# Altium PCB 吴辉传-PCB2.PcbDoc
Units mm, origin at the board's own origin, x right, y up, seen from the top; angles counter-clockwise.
Board outline 80 x 60 mm, 2 copper layers (Top Layer, Bottom Layer); 29 components, 19 nets, 66 pads, 0 vias.
Unrouted connection lines stored in the file: 47.
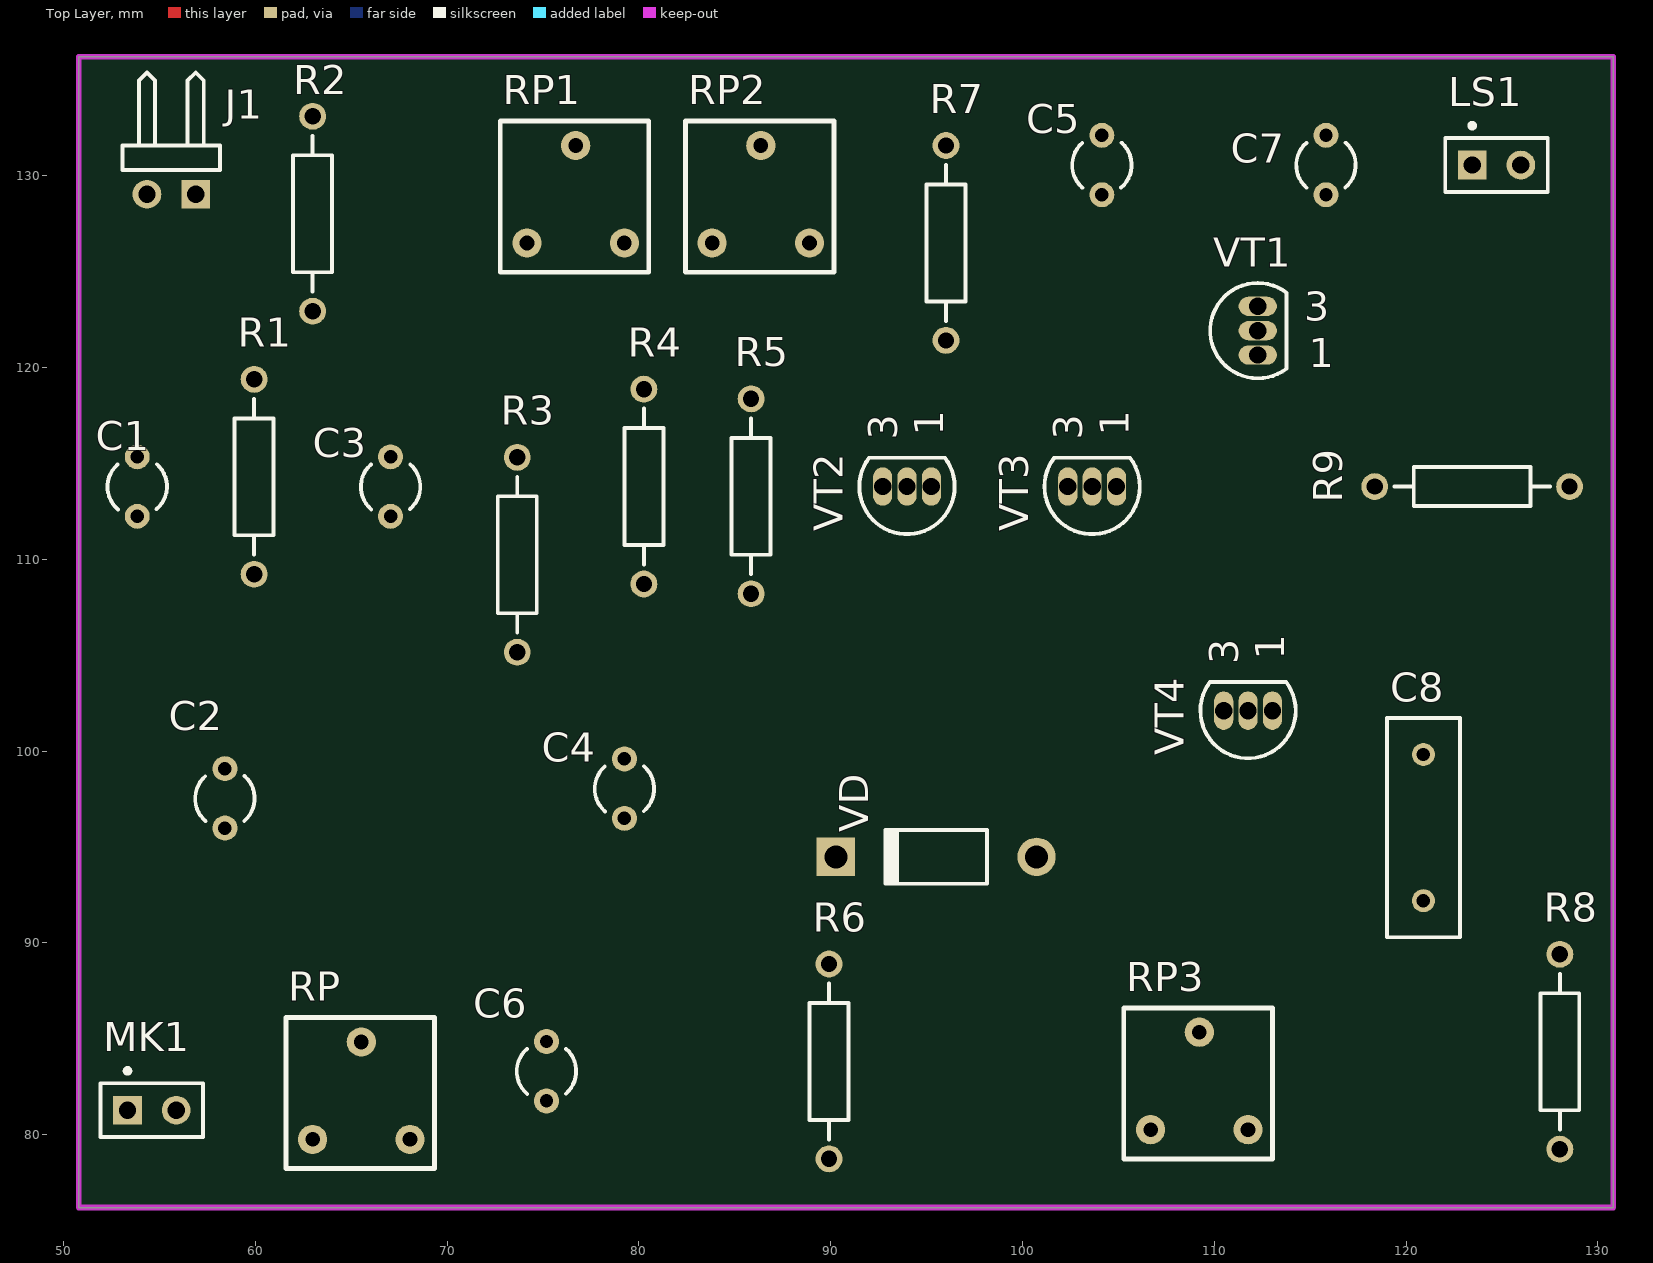
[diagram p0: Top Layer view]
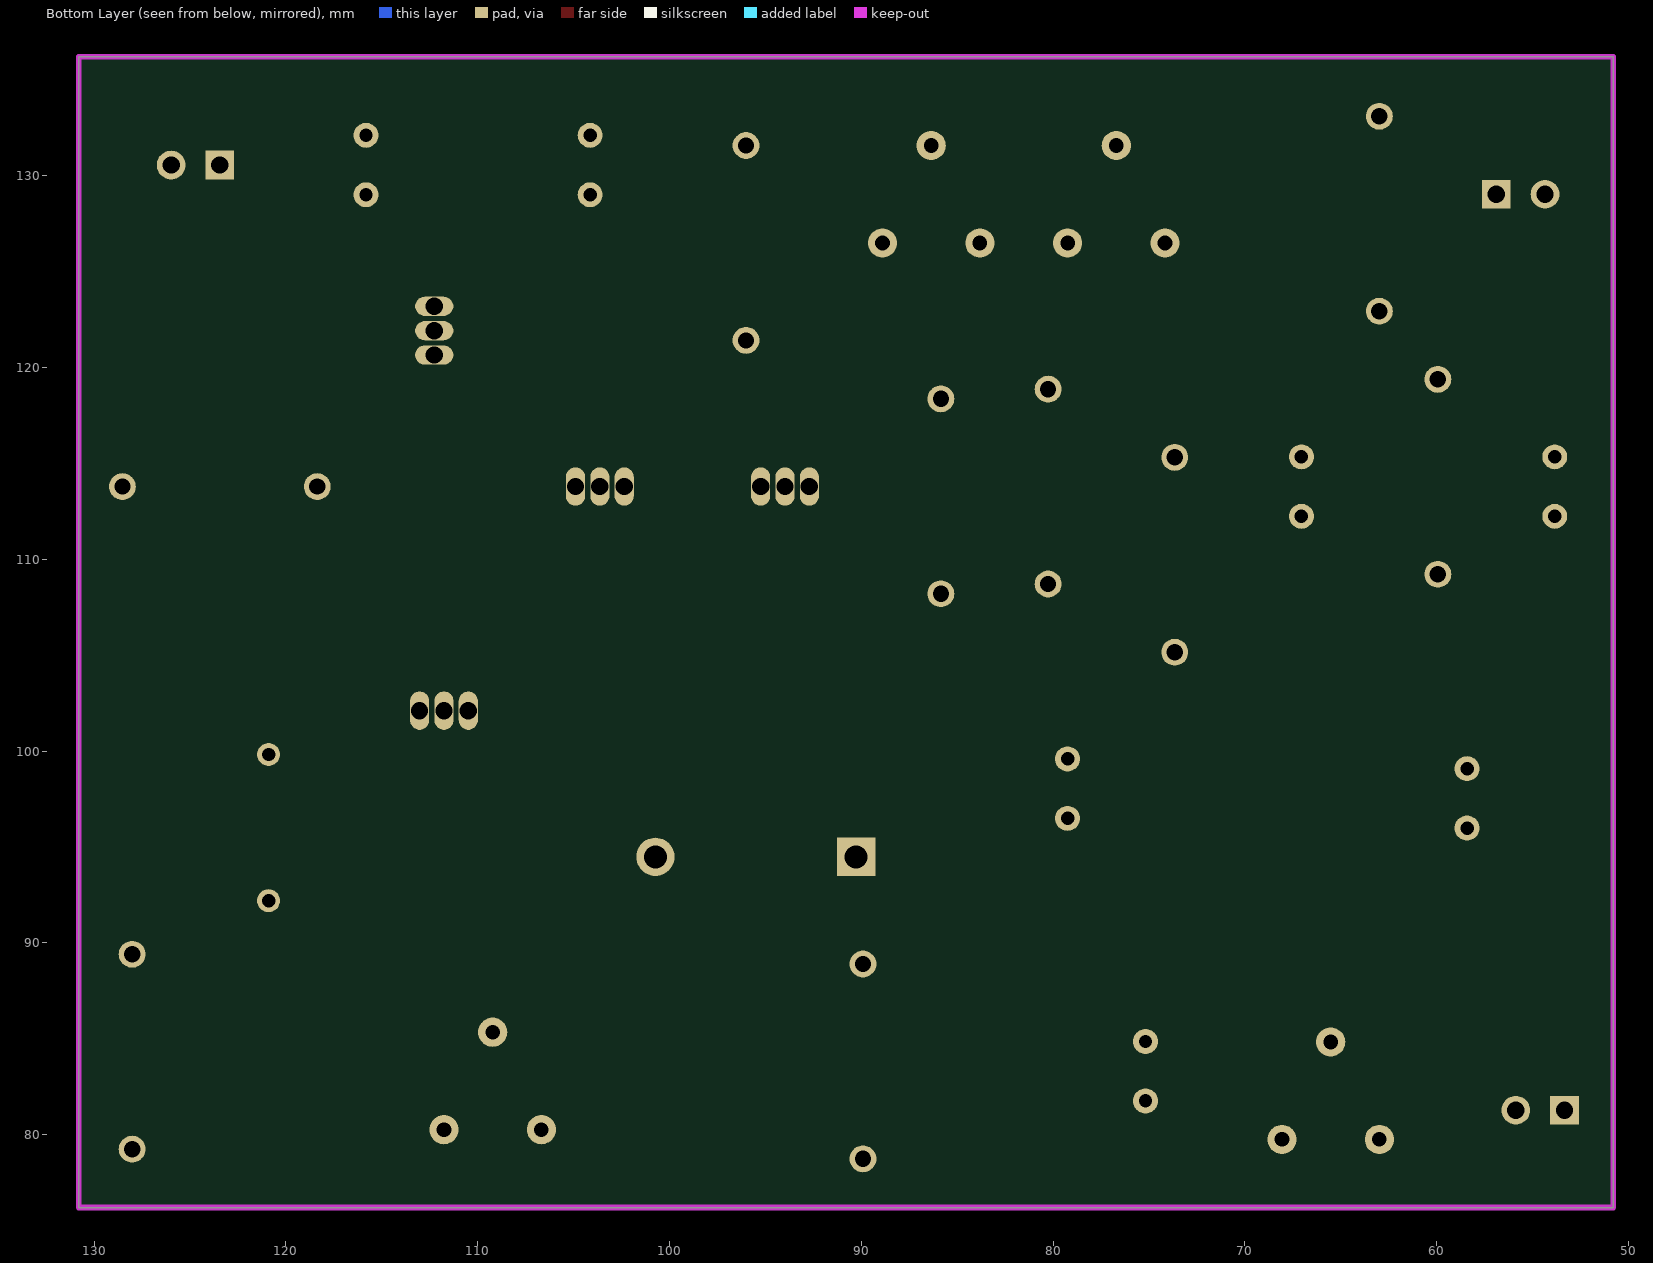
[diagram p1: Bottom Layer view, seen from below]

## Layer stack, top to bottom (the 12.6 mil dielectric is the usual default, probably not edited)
Top Layer: signal copper 0.0356
Dielectric: dielectric 0.32, FR-4, Dk 4.8
Bottom Layer: signal copper 0.0356

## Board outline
50.8,76.2 130.8,76.2 130.8,136.2 50.8,136.2

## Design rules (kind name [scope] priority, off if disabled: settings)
Clearance [All] p1: gap=0.2
ComponentClearance [All] p1: gap=0.254 collisioncheckmode=0
PolygonConnect [All] p1: connectstyle=Relief reliefconductorwidth=0.254 reliefentries=4 polygonreliefangle="90 Angle"
RoutingLayers [InNet('GND')] p1: top layer_v5=FALSE bottom layer_v5=TRUE
RoutingVias [All] p1: holewidth=0.6 width=1 viastyle="Through Hole" minholewidth=0.711 minwidth=1.27 maxholewidth=0.711 maxwidth=1.27
SolderMaskExpansion [All] p1: expansion=0.102
TestPointUsage [All] p1: valid=0 allowmultiple=FALSE
Testpoint [All] p1: side=15 testpointundercomponent=TRUE minsize=1.016 maxsize=2.54 preferedsize=1.524 minholesize=0 maxholesize=1.016 preferedholesize=0.813 testpointgrid=0.025 style=1023 order=1234567890
Width Width_2 [InNet('GND')] p1: maxlimit=1 minlimit=1 preferedwidth=1
Width Width_1 [InNet('VCC')] p2: maxlimit=1.5 minlimit=1.5 preferedwidth=1.5
Width [All] p3: maxlimit=1.2 minlimit=1.2 preferedwidth=1.2
16 further rules are at their usual default settings.

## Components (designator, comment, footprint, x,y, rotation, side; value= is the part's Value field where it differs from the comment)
C1 "10uF" BCY-W2/D3.1 53.848,113.792 r0 top
C2 "Cap Pol1" BCY-W2/D3.1 58.42,97.536 r0 top
C3 "Cap Pol1" BCY-W2/D3.1 67.056,113.792 r0 top
C4 "Cap Pol1" BCY-W2/D3.1 79.248,98.044 r0 top
C5 "Cap Pol1" BCY-W2/D3.1 104.14,130.556 r0 top
C6 "Cap Pol1" BCY-W2/D3.1 75.184,83.312 r0 top
C7 "Cap Pol1" BCY-W2/D3.1 115.824,130.556 r0 top
C8 "Cap" RAD-0.3 120.904,96.012 r90 top
J1 "MHDR1X" HDR1X2H 56.896,129.032 r180 top
LS1 "Speaker" PIN2 123.444,130.556 r0 top
MK1 "Mic" PIN2 53.34,81.28 r0 top
R1 "Res2" AXIAL-0.4 59.944,114.3 r90 top
R2 "Res2" AXIAL-0.4 62.992,128.016 r90 top
R3 "Res2" AXIAL-0.4 73.66,110.236 r90 top
R4 "Res2" AXIAL-0.4 80.264,113.792 r90 top
R5 "Res2" AXIAL-0.4 85.852,113.284 r90 top
R6 "Res2" AXIAL-0.4 89.916,83.82 r90 top
R7 "Res2" AXIAL-0.4 96.012,126.492 r90 top
R8 "Res2" AXIAL-0.4 128.016,84.328 r90 top
R9 "Res2" AXIAL-0.4 123.444,113.792 r180 top
RP "RPot" PCBComponent_1 65.532,82.296 r0 top
RP1 "RPot" PCBComponent_1 76.708,129.032 r0 top
RP2 "RPot" PCBComponent_1 86.36,129.032 r0 top
RP3 "" PCBComponent_1 109.22,82.804 r0 top
VD "4148" DIO10.46-5.3x2.8 95.504,94.488 r180 top
VT1 "9014" BCY-W3/E4 112.268,121.92 r0 top
VT2 "9014" BCY-W3/E4 93.98,113.792 r90 top
VT3 "8550" BCY-W3/E4 103.632,113.792 r90 top
VT4 "8550" BCY-W3/E4 111.76,102.108 r90 top

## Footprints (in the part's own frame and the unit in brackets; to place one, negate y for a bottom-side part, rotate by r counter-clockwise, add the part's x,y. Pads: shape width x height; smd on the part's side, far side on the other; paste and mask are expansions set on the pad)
AXIAL-0.4 [mm] "Resistor; 2 Leads"
  round 1.4 hole 0.85: 1(-5.08,0) 2(5.08,0)
  silkscreen extent -4.06,-1.02 4.06,1.02
BCY-W2/D3.1 [mm] "Crystal, Thru-Hole; 2 Leads; Body 3.1 x 8.2 mm (Dia.xH)"
  round 1.3 hole 0.7: 1(0,1.55) 2(0,-1.55)
  silkscreen extent -1.55,-1.19 1.55,1.17
BCY-W3/E4 [mm] "TO, Flat Index; 3 In-Line, Axial Leads; Body Dia. 4.7mm"
  oval 2x1 hole 0.9: 1(0,-1.27) 2(0,0) 3(0,1.27)
  silkscreen extent -2.48,-2.48 1.5,2.48
DIO10.46-5.3x2.8 [mm] "Diode, Axial; Body 5.2 x 2.7 mm (LxDia. max), Lead Dia. 0.86 mm (max)"
  round 2 hole 1.2: 1(-5.23,0)
  rect 2x2 hole 1.2: 2(5.23,0)
  silkscreen extent -2.65,-1.4 2.75,1.4
HDR1X2H [mm] "Connector; Header; 2 Position; Right Angle"
  rect 1.5x1.5 hole 0.9: 1(0,0)
  round 1.5 hole 0.9: 2(2.54,0)
  silkscreen extent -1.27,-6.35 3.81,-1.27
PCBComponent_1 [mil]
  round 60 hole 30: 1(100,-100) 2(0,100) 3(-100,-100)
  silkscreen extent -155,-160 150,150
PIN2 [mm] "Photosensitive Diode; 2 Leads"
  rect 1.5x1.5 hole 0.9: 1(0,0)
  round 1.5 hole 0.9: 2(2.54,0)
  silkscreen extent -1.4,-1.4 3.94,2.17
RAD-0.3 [mm] "Capacitor; 2 Leads"
  round 1.2 hole 0.7: 1(-3.81,0) 2(3.81,0)
  silkscreen extent -5.71,-1.91 5.71,1.91

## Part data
C1: library part "Cap Pol1", "Polarized Capacitor (Radial)"
C2 C3 C4 C5 C6 C7: "Polarized Capacitor (Radial)"
C8: "Capacitor"
J1: library part "Header 2H", "Header, 2-Pin, Right Angle"
LS1: "Loudspeaker"
MK1: library part Mic2, "Microphone"
R1 R2 R3 R4 R5 R6 R7 R8 R9: "Resistor"
RP RP1 RP2: "Potentiometer"
RP3: library part RPot, "Potentiometer"
VD: library part "Diode 1N4001", "1 Amp General Purpose Rectifier"
VT1 VT2: library part 2N3904, "NPN General Purpose Amplifier"
VT3 VT4: library part 2N3906, "PNP General Purpose Amplifier"

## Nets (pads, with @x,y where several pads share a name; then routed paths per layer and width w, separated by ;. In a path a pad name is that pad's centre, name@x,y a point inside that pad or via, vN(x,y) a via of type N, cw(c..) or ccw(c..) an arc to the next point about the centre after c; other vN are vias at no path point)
GND: C6.2 C7.2 J1.2 LS1.1 LS1.2 R9.2
NetC1_1: C1.1 R1.1 R2.1
NetC1_2: C1.2 C8.2 MK1.1 RP.2 VT1.1 VT4.3
NetC2_1: C2.1 MK1.2 R1.2
NetC2_2: C2.2 RP.3
NetC3_1: C3.1 RP.1
NetC3_2: C3.2 C8.1 R3.1 VT1.2
NetC4_1: C4.1 R3.2 R4.2 VT1.3
NetC4_2: C4.2 R5.2 R6.1 VT2.2
NetC5_2: C5.2 R7.2 VT2.3
NetC6_1: C6.1 R6.2
NetR4_1: R4.1 RP1.2
NetR5_1: R5.1 RP2.2
NetR8_1: R8.1 RP3.2
NetR8_2: R8.2 R9.1 VT4.2
NetRP3_1: RP3.1 RP3.3 VD.2
NetVD_1: VD.1 VT2.1 VT3.2
NetVT3_3: VT3.3 VT4.1
VCC: C5.1 C7.1 J1.1 R2.2 R7.1 RP1.1 RP1.3 RP2.1 RP2.3 VT3.1

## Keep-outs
Keep-Out Layer:
  the board outline again, w0.3

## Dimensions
50.8,76.2 to 50.8,136.2 on Mechanical 1
50.8,76.2 to 130.8,76.2 on Mechanical 1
